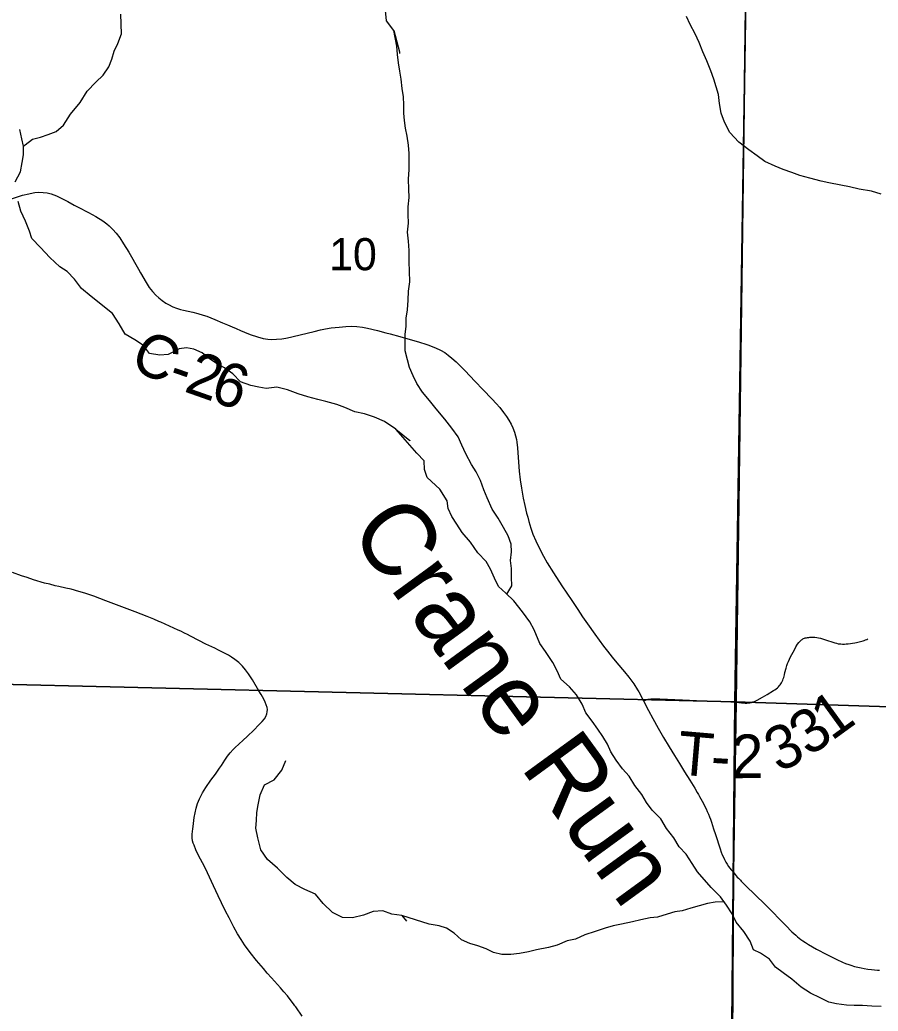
# Model space of a CAD drawing. Extents: x 0 to 34, y 0 to 22.
# Drawn here: x 24.137 to 25.255, y 18.367 to 19.658 of the extents above; entities that cross this region are included whole.
import ezdxf

# ---------------------------------------------------------------- set-up
doc = ezdxf.new("R2010")
doc.units = 0
for name, color, linetype in [('GM_X_Corporation', 7, 'Continuous'), ('GM_X_County_Road', 7, 'Continuous'), ('GM_X_County_Road_Text', 7, 'Continuous'), ('GM_X_Minor_River', 7, 'Continuous'), ('GM_X_Minor_River_Text', 7, 'Continuous'), ('GM_X_Section_Text', 7, 'Continuous'), ('GM_X_Township_Road', 7, 'Continuous'), ('GM_X_Township_Road_Text', 7, 'Continuous')]:
    doc.layers.add(name, color=color, linetype=linetype)

msp = doc.modelspace()

# ---------------------------------------------------------------- linework, layer by layer
at = {"layer": 'GM_X_Corporation'}
for points in [[(30.3167, 20.9), (25.1014, 20.9), (25.0988, 20.7425), (25.0847, 19.8351), (25.0701, 18.7696), (25.0668, 18.5474), (25.0619, 17.7438), (25.4012, 17.7333), (26.0747, 17.7146), (26.0759, 17.6934), (26.0745, 17.4524), (26.0677, 16.948), (26.0646, 16.863), (26.0683, 16.6823), (26.3378, 16.673), (27.0694, 16.6556)], [(26.0759, 17.6934), (26.0747, 17.7146), (25.4012, 17.7333), (25.0619, 17.7438), (25.0668, 18.5474), (25.0701, 18.7696), (25.0847, 19.8351), (25.0988, 20.7425), (24.9808, 20.7443), (24.1323, 20.7702), (24.1208, 20.7707), (23.5167, 20.7862), (23.5167, 14.7114)]]:
    msp.add_lwpolyline(points, dxfattribs=at)
for points in [[(25.0844, 19.7972), (25.0685, 18.7697), (24.0555, 18.7938), (24.0758, 19.8228)], [(25.0844, 19.7972), (26.1009, 19.7362), (26.0916, 18.7368), (25.0685, 18.7697)], [(25.0685, 18.7697), (25.0591, 17.7438), (24.0329, 17.7663), (24.0555, 18.7938)], [(26.0916, 18.7368), (26.075, 17.7146), (25.0591, 17.7438), (25.0685, 18.7697)]]:
    msp.add_lwpolyline(points, close=True, dxfattribs=at)
at = {"layer": 'GM_X_County_Road'}
for points in [[(24.1264, 19.4245), (24.1406, 19.4291), (24.1487, 19.4312), (24.1543, 19.4324), (24.1567, 19.4327), (24.1616, 19.433), (24.1677, 19.4328), (24.1725, 19.4322), (24.1778, 19.4309), (24.1847, 19.4285), (24.1925, 19.4247), (24.1995, 19.4208), (24.2077, 19.4164), (24.2132, 19.4135), (24.2265, 19.4067), (24.2363, 19.4013), (24.2452, 19.3959), (24.2506, 19.3918), (24.2534, 19.3895), (24.2582, 19.3847), (24.2627, 19.3796), (24.2672, 19.3737), (24.2723, 19.366), (24.279, 19.3549), (24.2917, 19.3328), (24.2945, 19.328), (24.3016, 19.3155), (24.3056, 19.3092), (24.3099, 19.3038), (24.3143, 19.2992), (24.318, 19.2958), (24.3224, 19.2922), (24.3275, 19.2886), (24.3308, 19.2868), (24.3365, 19.284), (24.3411, 19.2822), (24.3465, 19.2805), (24.3501, 19.2795), (24.3623, 19.2769), (24.3689, 19.2752), (24.3759, 19.2731), (24.3806, 19.2715), (24.3909, 19.2673), (24.4012, 19.263), (24.4074, 19.2603), (24.4138, 19.2577), (24.4189, 19.2555), (24.4247, 19.2532), (24.4298, 19.251), (24.4373, 19.248), (24.4468, 19.2447), (24.4541, 19.2427), (24.4603, 19.2418), (24.4653, 19.2415), (24.4716, 19.2416), (24.4785, 19.2422), (24.4834, 19.243), (24.4895, 19.2443), (24.4932, 19.2452), (24.5203, 19.2519), (24.5287, 19.2539), (24.5354, 19.2552), (24.5427, 19.2564), (24.5532, 19.2576), (24.5618, 19.2584), (24.5686, 19.2586), (24.576, 19.2584), (24.5833, 19.2576), (24.5899, 19.2563), (24.6032, 19.2531), (24.6139, 19.2502), (24.6193, 19.2487), (24.6319, 19.2453), (24.6576, 19.2378), (24.6658, 19.2352), (24.6687, 19.2342), (24.6785, 19.2305), (24.6852, 19.2273), (24.6905, 19.2242), (24.695, 19.221), (24.6998, 19.2171), (24.7053, 19.2122), (24.7097, 19.2078), (24.7166, 19.2008), (24.7304, 19.1865), (24.7403, 19.1762), (24.7524, 19.1637), (24.7574, 19.1582), (24.7622, 19.1526), (24.7672, 19.1463), (24.7712, 19.1409), (24.7742, 19.1362), (24.7773, 19.1309), (24.7793, 19.1264), (24.7815, 19.1207), (24.7829, 19.116), (24.784, 19.1113), (24.7846, 19.1076), (24.7854, 19.1003), (24.7867, 19.0817), (24.7877, 19.0699), (24.789, 19.0588), (24.7906, 19.0477), (24.7929, 19.0348), (24.795, 19.0251), (24.7973, 19.0154), (24.7987, 19.01), (24.8001, 19.0045), (24.8027, 18.9955), (24.8054, 18.9879), (24.8092, 18.9793), (24.8148, 18.9675), (24.8192, 18.9592), (24.8242, 18.9506), (24.8324, 18.9374), (24.8433, 18.9207), (24.8561, 18.9016), (24.864, 18.8897), (24.8702, 18.8804), (24.8764, 18.8711), (24.8861, 18.8575), (24.8972, 18.8422), (24.9027, 18.8354), (24.9087, 18.8276), (24.9146, 18.8205), (24.9246, 18.8087), (24.9305, 18.8016), (24.9331, 18.7981), (24.9367, 18.7931), (24.9416, 18.7853), (24.9432, 18.7826), (24.9496, 18.7709)], [(24.9496, 18.7709), (24.9559, 18.7585), (24.9616, 18.7478), (24.9684, 18.7354), (24.9756, 18.7231), (24.9829, 18.7109), (24.9898, 18.6999), (24.9962, 18.6894), (25.0029, 18.6784), (25.0097, 18.6676), (25.0163, 18.657), (25.0195, 18.6516), (25.0211, 18.649), (25.0226, 18.6463), (25.0242, 18.6435), (25.0259, 18.6404), (25.0276, 18.6371), (25.0295, 18.6335), (25.031, 18.6302), (25.0326, 18.6269), (25.034, 18.6235), (25.0355, 18.62), (25.0367, 18.6166), (25.0379, 18.613), (25.0408, 18.6042), (25.0431, 18.5969), (25.0493, 18.578), (25.0507, 18.5738), (25.0521, 18.5704), (25.0535, 18.5674), (25.0551, 18.5641), (25.0568, 18.561), (25.0585, 18.5583), (25.0604, 18.5554), (25.0619, 18.5532), (25.0638, 18.5508), (25.0653, 18.5489), (25.067, 18.5468)], [(25.067, 18.5468), (25.0687, 18.5448), (25.0702, 18.5431), (25.0716, 18.5415), (25.0732, 18.5398), (25.0744, 18.5386), (25.0757, 18.5372), (25.0769, 18.536), (25.0788, 18.5341), (25.0841, 18.5289), (25.0936, 18.5196), (25.1091, 18.5043), (25.1349, 18.4783), (25.1428, 18.4703), (25.1478, 18.4656), (25.15, 18.4638), (25.1522, 18.462), (25.1545, 18.4602), (25.1572, 18.4584), (25.1607, 18.4561), (25.1646, 18.4537), (25.1748, 18.4477), (25.1885, 18.4404), (25.2013, 18.434), (25.2087, 18.4307), (25.2127, 18.429), (25.2168, 18.4275), (25.2197, 18.4266), (25.2244, 18.4252), (25.2287, 18.424), (25.2331, 18.4231), (25.2371, 18.4223), (25.2416, 18.4217), (25.2465, 18.4211), (25.2506, 18.4207), (25.2541, 18.4204), (25.2571, 18.4202)]]:
    msp.add_lwpolyline(points, dxfattribs=at)
at = {"layer": 'GM_X_Minor_River'}
for points in [[(24.1417, 19.4925), (24.144, 19.4948), (24.1538, 19.5021), (24.164, 19.5048), (24.1742, 19.5083), (24.1844, 19.5122), (24.1942, 19.5206), (24.2032, 19.5347), (24.2156, 19.55), (24.225, 19.5645), (24.2359, 19.5763), (24.2457, 19.5855), (24.2532, 19.5965), (24.2569, 19.6064), (24.2599, 19.6167), (24.2648, 19.6266), (24.2696, 19.6392), (24.2687, 19.665)], [(24.6244, 19.6438), (24.6149, 19.6563), (24.6136, 19.6696)], [(25.2591, 19.4305), (25.2466, 19.4346), (25.2303, 19.4371), (25.2178, 19.4403), (25.2064, 19.4421), (25.1909, 19.4454), (25.1807, 19.4475), (25.1663, 19.4515), (25.153, 19.4548), (25.1428, 19.4589), (25.1314, 19.4625), (25.1212, 19.467), (25.1075, 19.4733), (25.0976, 19.4804), (25.0866, 19.4882), (25.0736, 19.4983), (25.0618, 19.5107), (25.0549, 19.5243), (25.0506, 19.536), (25.0486, 19.5488), (25.047, 19.5602), (25.0412, 19.5802), (25.0373, 19.5911), (25.0319, 19.604), (25.0269, 19.616), (25.0222, 19.6281), (25.0168, 19.6394), (25.0103, 19.6515), (25.0057, 19.6617)], [(24.7714, 18.9099), (24.7781, 18.9205), (24.7777, 18.9318), (24.7776, 18.9432), (24.7763, 18.9538), (24.7774, 18.9648), (24.7773, 18.975), (24.7734, 18.9856), (24.7673, 18.9965), (24.76, 19.0089), (24.7523, 19.0206), (24.7458, 19.0353), (24.7415, 19.0455), (24.7373, 19.0576), (24.7315, 19.0689), (24.7254, 19.0787), (24.7181, 19.0926), (24.713, 19.1039), (24.708, 19.1145), (24.7, 19.1261), (24.6908, 19.1378), (24.6794, 19.1509), (24.6706, 19.1618), (24.6614, 19.1727), (24.6541, 19.184), (24.6495, 19.1942), (24.6449, 19.2047), (24.6421, 19.2149), (24.639, 19.2267), (24.6389, 19.2361), (24.6392, 19.2479), (24.6402, 19.2585), (24.6402, 19.2691), (24.6419, 19.2801), (24.643, 19.2926), (24.6432, 19.3044), (24.645, 19.3165), (24.6449, 19.3302), (24.6441, 19.3426), (24.6443, 19.3574), (24.6434, 19.3692), (24.6422, 19.3813), (24.6432, 19.3926), (24.6428, 19.404), (24.643, 19.4142), (24.6441, 19.4264), (24.644, 19.437), (24.6435, 19.4502), (24.6441, 19.4627), (24.6444, 19.4734), (24.6443, 19.4836), (24.6435, 19.4942), (24.6415, 19.5059), (24.6395, 19.5165), (24.6383, 19.5263), (24.6374, 19.5362), (24.6374, 19.5468), (24.6369, 19.5574), (24.6353, 19.568), (24.6337, 19.5801), (24.6321, 19.5907), (24.6305, 19.6017), (24.6292, 19.6122), (24.6284, 19.6232), (24.6244, 19.6438), (24.6318, 19.6157), (24.6315, 19.6138)], [(24.131, 19.4465), (24.1378, 19.4595), (24.1403, 19.472), (24.1418, 19.4819), (24.1417, 19.4929), (24.1397, 19.5028), (24.137, 19.5149)], [(24.6268, 19.1246), (24.612, 19.1347), (24.5991, 19.1403), (24.5861, 19.1444), (24.5736, 19.147), (24.5603, 19.1526), (24.55, 19.1567), (24.5356, 19.1608), (24.5253, 19.163), (24.5121, 19.1667), (24.4995, 19.1708), (24.4858, 19.1756), (24.4718, 19.1793), (24.4578, 19.1777), (24.4483, 19.1792), (24.438, 19.1814), (24.4247, 19.1862), (24.4144, 19.1968), (24.4037, 19.2043), (24.3942, 19.2096), (24.3843, 19.2163), (24.3748, 19.2239), (24.3638, 19.2287), (24.3543, 19.2306), (24.3448, 19.2293), (24.3305, 19.222), (24.3195, 19.2208), (24.3058, 19.223), (24.2982, 19.2336), (24.2871, 19.2411), (24.2745, 19.2482), (24.2665, 19.2618), (24.2577, 19.2754), (24.2302, 19.2973), (24.2173, 19.3078), (24.2085, 19.3199), (24.1989, 19.3297), (24.1894, 19.3361), (24.1761, 19.3482), (24.1642, 19.361), (24.1528, 19.3727), (24.1497, 19.3825), (24.1446, 19.3954), (24.1385, 19.4083), (24.135, 19.4211)], [(24.75, 18.9425), (24.7446, 18.9523), (24.7339, 18.9636), (24.7243, 18.9775), (24.7133, 18.9899), (24.7064, 19.0008), (24.6999, 19.011), (24.6952, 19.0215), (24.6936, 19.0314), (24.6841, 19.0464), (24.6677, 19.0618), (24.6642, 19.072), (24.6637, 19.0833), (24.6542, 19.0935), (24.6268, 19.1246), (24.6453, 19.1097), (24.645, 19.1093)], [(25.2592, 18.3731), (25.2467, 18.3734), (25.2346, 18.3744), (25.224, 18.3743), (25.2138, 18.3746), (25.201, 18.3763), (25.1911, 18.3785), (25.1794, 18.3841), (25.1672, 18.3904), (25.1547, 18.3982), (25.1429, 18.4083), (25.1314, 18.4169), (25.1216, 18.424), (25.1135, 18.4345), (25.1021, 18.4423), (25.0926, 18.4468), (25.0884, 18.4581), (25.0803, 18.4705), (25.0704, 18.4825), (25.065, 18.4935), (25.0577, 18.5048), (25.0497, 18.5157), (25.0375, 18.528), (25.0199, 18.5483), (25.013, 18.5589), (25.005, 18.5713), (24.9958, 18.581), (24.9889, 18.5927), (24.9794, 18.6047), (24.9721, 18.6172), (24.9606, 18.6284), (24.9534, 18.6385), (24.9472, 18.6491), (24.938, 18.6607), (24.9308, 18.6728), (24.922, 18.6825), (24.9139, 18.6935), (24.907, 18.7044), (24.9024, 18.7145), (24.8967, 18.7243), (24.8898, 18.7341), (24.8825, 18.7443), (24.8745, 18.7552), (24.8698, 18.7665), (24.8622, 18.7789), (24.853, 18.789), (24.8416, 18.7992), (24.8369, 18.8101), (24.8312, 18.821), (24.822, 18.8349), (24.8143, 18.8455), (24.807, 18.8632), (24.8016, 18.8737), (24.792, 18.8869), (24.7806, 18.9012), (24.7703, 18.9109), (24.7608, 18.9199), (24.7554, 18.9305), (24.75, 18.9425)], [(24.6345, 18.4915), (24.6216, 18.4933), (24.6099, 18.4974), (24.5974, 18.4966), (24.5849, 18.4919), (24.5705, 18.4884), (24.5572, 18.4887), (24.5443, 18.4951), (24.5321, 18.5071), (24.5221, 18.5192), (24.5085, 18.5252), (24.4959, 18.5316), (24.4848, 18.541), (24.4726, 18.5531), (24.4597, 18.5644), (24.4512, 18.5768), (24.447, 18.5927), (24.4446, 18.6052), (24.4453, 18.6151), (24.446, 18.6254), (24.4474, 18.6356), (24.45, 18.6486), (24.456, 18.6615), (24.4684, 18.668), (24.4786, 18.6806), (24.4834, 18.6932)], [(25.0546, 18.509), (25.0429, 18.5088), (25.0327, 18.5068), (25.0218, 18.504), (25.0113, 18.5009), (24.9999, 18.4973), (24.9901, 18.4961), (24.9803, 18.493), (24.9679, 18.4894), (24.9581, 18.4882), (24.946, 18.4858), (24.935, 18.483), (24.9207, 18.4802), (24.9101, 18.4778), (24.8996, 18.4751), (24.8864, 18.4704), (24.8732, 18.4661), (24.8608, 18.4607), (24.8502, 18.4583), (24.837, 18.4528), (24.8257, 18.4497), (24.8102, 18.4469), (24.7997, 18.4441), (24.788, 18.4421), (24.7767, 18.4404), (24.7649, 18.4407), (24.7543, 18.4432), (24.7445, 18.4481), (24.7338, 18.4517), (24.7232, 18.455), (24.7126, 18.4599), (24.7027, 18.4685), (24.6928, 18.4748), (24.6833, 18.4781), (24.6701, 18.4799), (24.6345, 18.4915), (24.6409, 18.4841)]]:
    msp.add_lwpolyline(points, dxfattribs=at)
at = {"layer": 'GM_X_Township_Road'}
for points in [[(24.505, 18.3602), (24.4965, 18.3724), (24.4954, 18.3739), (24.4946, 18.3749), (24.4857, 18.3868), (24.481, 18.3918), (24.4766, 18.397), (24.4651, 18.4101), (24.4593, 18.4165), (24.4544, 18.4222), (24.4456, 18.4326), (24.4371, 18.4433), (24.4298, 18.4534), (24.4253, 18.46), (24.4207, 18.4674), (24.4159, 18.4761), (24.4096, 18.4882), (24.4051, 18.4971), (24.3999, 18.5077), (24.3954, 18.5172), (24.3894, 18.5302), (24.3842, 18.5415), (24.3814, 18.547), (24.3771, 18.556), (24.3704, 18.5686), (24.3663, 18.577), (24.364, 18.5828), (24.363, 18.5857), (24.3622, 18.5887), (24.3618, 18.5924), (24.3617, 18.5973), (24.3624, 18.6041), (24.3628, 18.6072), (24.3644, 18.6189), (24.3655, 18.625), (24.3669, 18.631), (24.3687, 18.637), (24.3711, 18.6434), (24.375, 18.6511), (24.3793, 18.658), (24.3861, 18.6676), (24.3919, 18.6756), (24.3945, 18.6791), (24.3973, 18.6832), (24.3997, 18.6868), (24.404, 18.6935), (24.4074, 18.6987), (24.411, 18.703), (24.4152, 18.7075), (24.4173, 18.7098), (24.4227, 18.7149), (24.4275, 18.7194), (24.4336, 18.7247), (24.4421, 18.7329), (24.4486, 18.7395), (24.4529, 18.744), (24.4556, 18.7474), (24.4575, 18.7506), (24.4589, 18.7538), (24.4594, 18.7566), (24.4597, 18.7595), (24.4591, 18.7624), (24.458, 18.7657), (24.4566, 18.769), (24.4548, 18.7729), (24.4514, 18.7791), (24.4486, 18.7837), (24.4402, 18.7981), (24.4349, 18.806), (24.4309, 18.8114), (24.427, 18.816), (24.4222, 18.8208), (24.4173, 18.8249), (24.4129, 18.8279), (24.4087, 18.8305), (24.3961, 18.837), (24.391, 18.8394), (24.3792, 18.8448), (24.3702, 18.8495), (24.3595, 18.8552), (24.3556, 18.8572), (24.3517, 18.8591), (24.3467, 18.8615), (24.3433, 18.8631), (24.3321, 18.8681), (24.3208, 18.8731), (24.318, 18.8743), (24.3117, 18.877), (24.3031, 18.8806), (24.2875, 18.8866), (24.2701, 18.8932), (24.2492, 18.9012), (24.2335, 18.9071), (24.2217, 18.9111), (24.214, 18.9134), (24.2038, 18.9161), (24.1971, 18.9176), (24.188, 18.9197), (24.1832, 18.9208), (24.176, 18.9227), (24.1694, 18.9243), (24.1551, 18.9285), (24.1468, 18.9313), (24.1391, 18.9338), (24.1274, 18.9379)], [(25.0703, 18.769), (25.0771, 18.7683), (25.082, 18.7679), (25.0842, 18.7679), (25.0863, 18.7681), (25.0882, 18.7683), (25.0902, 18.7688), (25.092, 18.7694), (25.0939, 18.7701), (25.0958, 18.7709), (25.0977, 18.7719), (25.1047, 18.7757), (25.1105, 18.7791), (25.119, 18.7842), (25.1207, 18.7854), (25.1223, 18.7865), (25.1239, 18.7878), (25.1252, 18.789), (25.1263, 18.7902), (25.1273, 18.7915), (25.1283, 18.7928), (25.1293, 18.7945), (25.1301, 18.7961), (25.1309, 18.7978), (25.1315, 18.7995), (25.1321, 18.8013), (25.1326, 18.8032), (25.133, 18.8049), (25.1337, 18.8078), (25.1352, 18.8136), (25.1362, 18.8168), (25.1371, 18.8194), (25.1382, 18.822), (25.1396, 18.825), (25.1411, 18.8281), (25.146, 18.8374), (25.1481, 18.8412), (25.1502, 18.8445), (25.1519, 18.8468), (25.1527, 18.8478), (25.1535, 18.8486), (25.1543, 18.8494), (25.1552, 18.8501), (25.1561, 18.8508), (25.1571, 18.8514), (25.158, 18.8519), (25.159, 18.8524), (25.1602, 18.8528), (25.1617, 18.8531), (25.1633, 18.8534), (25.1647, 18.8535), (25.1663, 18.8537), (25.1681, 18.8537), (25.1699, 18.8537), (25.1725, 18.8536), (25.1751, 18.8534), (25.1776, 18.8529), (25.1801, 18.8524), (25.1852, 18.8509), (25.1986, 18.8464), (25.2007, 18.8458), (25.203, 18.8453), (25.2048, 18.8451), (25.2067, 18.8449), (25.2089, 18.8448), (25.2111, 18.8448), (25.2135, 18.8449), (25.2161, 18.8451), (25.2191, 18.8455), (25.2218, 18.8458), (25.2247, 18.8463), (25.2269, 18.8468), (25.2287, 18.8472), (25.2305, 18.8476), (25.2322, 18.848), (25.2338, 18.8484), (25.2356, 18.849), (25.2371, 18.8495), (25.2387, 18.8501), (25.2403, 18.8508), (25.2418, 18.8514)], [(24.9496, 18.7709), (24.9557, 18.7731), (24.959, 18.7736), (24.9615, 18.7737), (24.964, 18.7737), (24.9707, 18.7736), (25.0005, 18.7723), (25.0367, 18.7705), (25.0506, 18.7701), (25.0568, 18.77), (25.0632, 18.7697), (25.0703, 18.769)]]:
    msp.add_lwpolyline(points, dxfattribs=at)

# ---------------------------------------------------------------- texts
at = {"layer": 'GM_X_County_Road_Text'}
for s, rotation, p in [('C', 332.8712, (24.2778, 19.2065)), ('2', 340.5258, (24.3495, 19.1742)), ('6', 340.9002, (24.3829, 19.1624)), ('-', 341.1488, (24.3276, 19.1817))]:
    msp.add_text(s, height=0.0568, rotation=rotation, dxfattribs=at).set_placement(p)
at = {"layer": 'GM_X_Minor_River_Text'}
msp.add_text('Crane Run', height=0.09469, rotation=306.0663, dxfattribs=at).set_placement((24.5643, 18.9919))
at = {"layer": 'GM_X_Section_Text'}
msp.add_text('10', height=0.04186, rotation=0, dxfattribs=at).set_placement((24.5399, 19.3315))
at = {"layer": 'GM_X_Township_Road_Text'}
for s, rotation, p in [('1', 35.9276, (25.1944, 18.7179)), ('3', 35.1911, (25.1651, 18.6973)), ('T', 355.0677, (24.9921, 18.6753)), ('3', 26.2489, (25.1254, 18.6769)), ('2', 0.7608, (25.0639, 18.67)), ('-', 356.6315, (25.0361, 18.6715))]:
    msp.add_text(s, height=0.0568, rotation=rotation, dxfattribs=at).set_placement(p)

doc.saveas('drawing.dxf')
